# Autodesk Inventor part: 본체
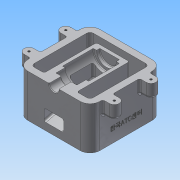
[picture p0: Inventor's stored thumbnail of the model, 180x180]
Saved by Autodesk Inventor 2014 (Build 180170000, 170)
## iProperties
Created: 2018-01
Part Number: 본체
Material: 알루미늄 6061
Document SubType Name: Modeling
Designer: 601-24
Density: 2.71 g/cm^3
Appearance: 알루미늄 - 평지
Mass: 998.903 g
Surface Area: 834.406 cm^2
Volume: 368.599 cm^3
Author: 601-24
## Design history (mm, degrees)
sketch "스케치1"
  geometry: L1 (-55, -55)-(55, -55); L2 (55, -55)-(55, 55); L3 (55, 55)-(-55, 55); L4 (-55, 55)-(-55, -55); L5 (-55, -55)-(55, 55); L6 (55, -55)-(-55, 55); 1 further point
  constraints: 12 end point, 2 midpoint, 2 parallel, 1 horizontal, 1 perpendicular
  dimensions: "d0" = 110 distance between parallel lines of L1 L3; "d1" = 110 distance between parallel lines of L4 L2
extrude "돌출1" new body sketch "스케치1" stored distance "d2" = 65; taper "d3" = 0 deg
sketch "스케치2"
  geometry: L1 (-55, -55)-(55, -55) reference; L2 (55, -55)-(55, 55) reference; L3 (55, 55)-(-55, 55) reference; L4 (-55, 55)-(-55, -55) reference; L5 (-55, -55)-(55, -55) reference; L6 (55, -55)-(55, 55) reference; L7 (55, 55)-(-55, 55) reference; L8 (-55, 55)-(-55, -55) reference; L9 (-45, 45)-(45, 45); L10 (45, 45)-(45, -45); L11 (45, -45)-(-45, -45); L12 (-45, -45)-(-45, 45); L13 (-25, 35)-(25, 35); L14 (25, 35)-(25, -45); L15 (25, -45)-(-25, -45); L16 (-25, -45)-(-25, 35); 1 further point
  constraints: 16 end point, 4 parallel, 2 horizontal, 2 perpendicular
  dimensions: "d4" = 10 distance between parallel lines of L9 L3; "d5" = 10 distance between parallel lines of L4 L12; "d6" = 10 distance between parallel lines of L1 L11; "d7" = 10 distance between parallel lines of L2 L10; "d8" = 50 distance between parallel lines of L14 L16; "d9" = 30 distance between parallel lines of L4 L16; "d10" = 20 distance between parallel lines of L3 L13; "d11" = 10 distance between parallel lines of L1 L15
extrude "돌출2" cut sketch "스케치2" stored distance "d12" = 65; taper "d13" = 0 deg
sketch "스케치3"
  geometry: L1 (-45, -32.5)-(35, -32.5) reference; L2 (-45, -32.5)-(-45, 32.5) reference; L3 (35, 32.5)-(-45, 32.5) reference; L4 (35, 32.5)-(35, -32.5) reference; L5 (-55, -32.5)-(55, -32.5) reference; L6 (55, 32.5)-(-55, 32.5) reference; L7 (-45, -23.936)-(35, -2.5); 1 further point
  constraints: 2 end point, 2 point on line
  dimensions: "d14" = 30 distance from line of L5 L7.end; "d15" = 105 deg angle of L2 L7
extrude "돌출3" cut sketch "스케치3" stored distance "d16" = 65; taper "d17" = 0 deg
sketch "스케치4"
  geometry: L1 (0, 0)-(110, 0) reference; L2 (110, -65)-(0, -65) reference; L3 (0, -65)-(0, 0) reference; L4 (0, 0)-(110, 0) reference; L5 (110, 0)-(110, -65) reference; C1 r 7.5 at (55, 0); 1 further point
  constraints: 1 centre point, 1 horizontal alignment, 1 vertical alignment
  dimensions: "d18" = 15 diameter of C1
extrude "돌출4" cut sketch "스케치4" distance "d19" = 19; taper "d20" = 0 deg
sketch "스케치5"
  geometry: C1 r 16 at (55, 0); A1 r 7.5 centre (55, 0) between (47.5, 0) and (62.5, 0) reference; 1 further point
  constraints: 1 centre point, 1 coincident
  dimensions: "d21" = 32 diameter of C1
extrude "돌출5" cut sketch "스케치5" distance "d22" = 14; taper "d23" = 0 deg
sketch "스케치6"
  geometry: C1 r 20 at (55, 0); A1 r 16 centre (55, 0) between (39, 0) and (71, 0) reference; 1 further point
  constraints: 1 centre point, 1 coincident
  dimensions: "d24" = 40 diameter of C1
extrude "돌출6" cut sketch "스케치6" distance "d25" = 47; taper "d26" = 0 deg
sketch "스케치7"
  geometry: C1 r 15 at (55, 0); A1 r 20 centre (55, 0) between (35, 0) and (75, 0) reference; 1 further point
  constraints: 1 centre point, 1 coincident
  dimensions: "d27" = 30 diameter of C1
extrude "돌출7" cut sketch "스케치7" distance "d28" = 5; taper "d29" = 0 deg
sketch "스케치8"
  geometry: L1 (35, -2.5)-(-45, -23.936) reference; L2 (-55, 32.5)-(-55, -32.5) reference; L3 (20, -1.343)-(-55, -21.439); L4 (-17, 22.5)-(20, 22.5); L5 (-22, 16.5)-(-22, 32.5) reference; L6 (25, 17.5)-(25, 32.5) reference; L7 (-22, 12.5)-(25, 12.5) reference; L8 (-17, 22.5)-(-17, 6.743); L9 (20, 22.5)-(20, -1.343); L10 (-17, 6.743)-(-55, -3.439); 3 further points
  constraints: 10 end point, 3 parallel, 2 midpoint, 2 perpendicular, 2 point on line, 1 vertical alignment
  dimensions: "d30" = 5 distance between parallel lines of L1 L3; "d31" = 18 distance of L3.end L10.end; "d32" = 37 distance of L4.start L4.end; "d33" = 10 distance from line of point (1.5, 12.5) L4
extrude "돌출8" cut sketch "스케치8" stored distance "d34" = 30; taper "d35" = 0 deg
fillet "모깎기1" dims "d36" = 1
chamfer "모따기1" distance "d37" = 1; stored, may be unused: second distance "d38" = 2, angle "d39" = 45 deg
fillet "모깎기2" dims "d40" = 15
fillet "모깎기3" dims "d41" = 5
fillet "모깎기5" dims "d43" = 3
fillet "모깎기6" dims "d44" = 3
fillet "모깎기7" dims "d45" = 3
fillet "모깎기8" dims "d46" = 3
fillet "모깎기9" dims "d47" = 3
fillet "모깎기10" dims "d48" = 3
sketch "스케치9"
  geometry: L1 (-55, 40)-(-55, -40) reference; L2 (-40, -55)-(-8.5, -55) reference; L3 (-65, 35.5)-(-55, 35.5); L4 (-65, 20.5)-(-55, 20.5); L5 (-65, -20.5)-(-55, -20.5); L6 (-65, -35.5)-(-55, -35.5); A1 r 7.5 centre (-65, -28) between (-65, -20.5) and (-65, -35.5); A2 r 7.5 centre (-65, 28) between (-65, 35.5) and (-65, 20.5); 1 further point
  constraints: 8 end point, 4 perpendicular, 4 point on circle, 4 point on line, 4 tangent, 2 centre point
  dimensions: "d49" = 15 diameter of A1; "d50" = 15 diameter of A2; "d51" = 10 distance from line of A2.centre L1; "d52" = 10 distance from line of A1.centre L1; "d53" = 27 distance from line of A1.centre L2; "d54" = 56 distance of A1.centre A2.centre
extrude "돌출9" join sketch "스케치9" distance "d55" = 20; taper "d56" = 0 deg
fillet "모깎기11" dims "d57" = 3
fillet "모깎기12" dims "d58" = 3
fillet "모깎기13" dims "d59" = 3
fillet "모깎기14" dims "d60" = 3
sketch "스케치10"
  geometry: A1 r 7.5 centre (-65, 28) between (-65, 35.5) and (-65, 20.5) reference; A2 r 7.5 centre (-65, -28) between (-65, -20.5) and (-65, -35.5) reference; A3 r 7.5 centre (65, -28) between (65, -35.5) and (65, -20.5) reference; A4 r 7.5 centre (65, 28) between (65, 20.5) and (65, 35.5) reference; 5 further points
  constraints: 4 coincident
hole "구멍1" sketch "스케치10" at (-65, 28), (65, -28), (65, 28), (-65, -28) diameter "d61" = 3.242; stored, may be unused: countersink angle "d65" = 90 deg, drill point angle "d67" = 118 deg; dims "d62" = 9, "d63" = 4, "d64" = 2, "d66" = 11
sketch "스케치11"
  geometry: L1 (0, 80)-(0, 0) reference; L2 (-65, -15)-(0, -15) reference; 2 further points
  constraints: 1 other
  dimensions: "d68" = 55 distance from line of point (-20, 40) L2; "d69" = 20 distance from line of point (-20, 40) L1
feature "엠보싱1" sketch "스케치11" dims "d0" = 110, "d1" = 110, "d4" = 10, "d70" = 0.5, "d71" = 0
node "솔리드1"
mirror "대칭1"
node "투영된 루프1"
node "투영된 루프2"
node "절단 모서리 투영1"
